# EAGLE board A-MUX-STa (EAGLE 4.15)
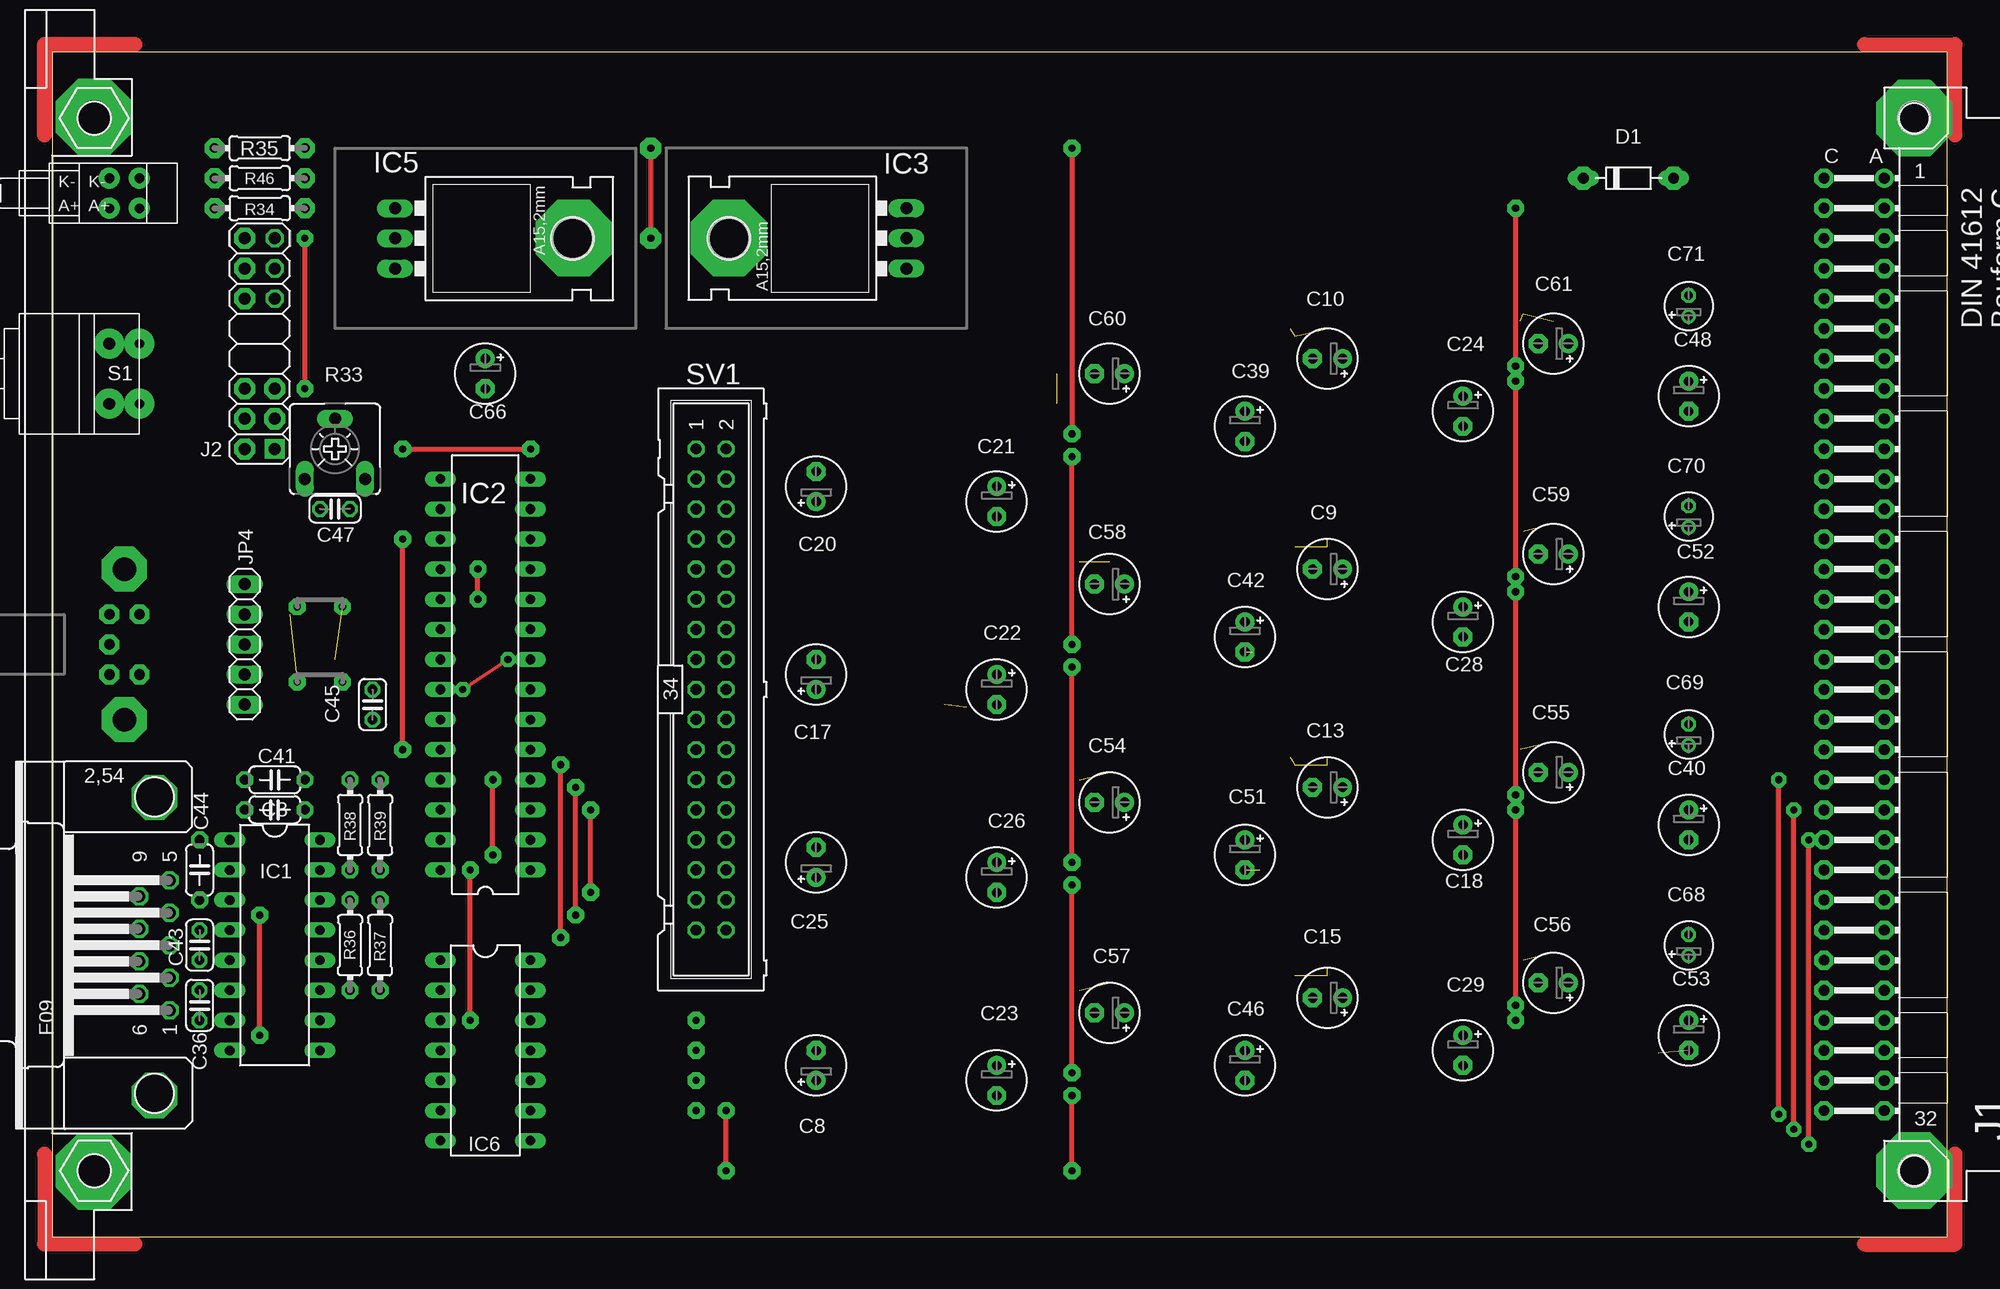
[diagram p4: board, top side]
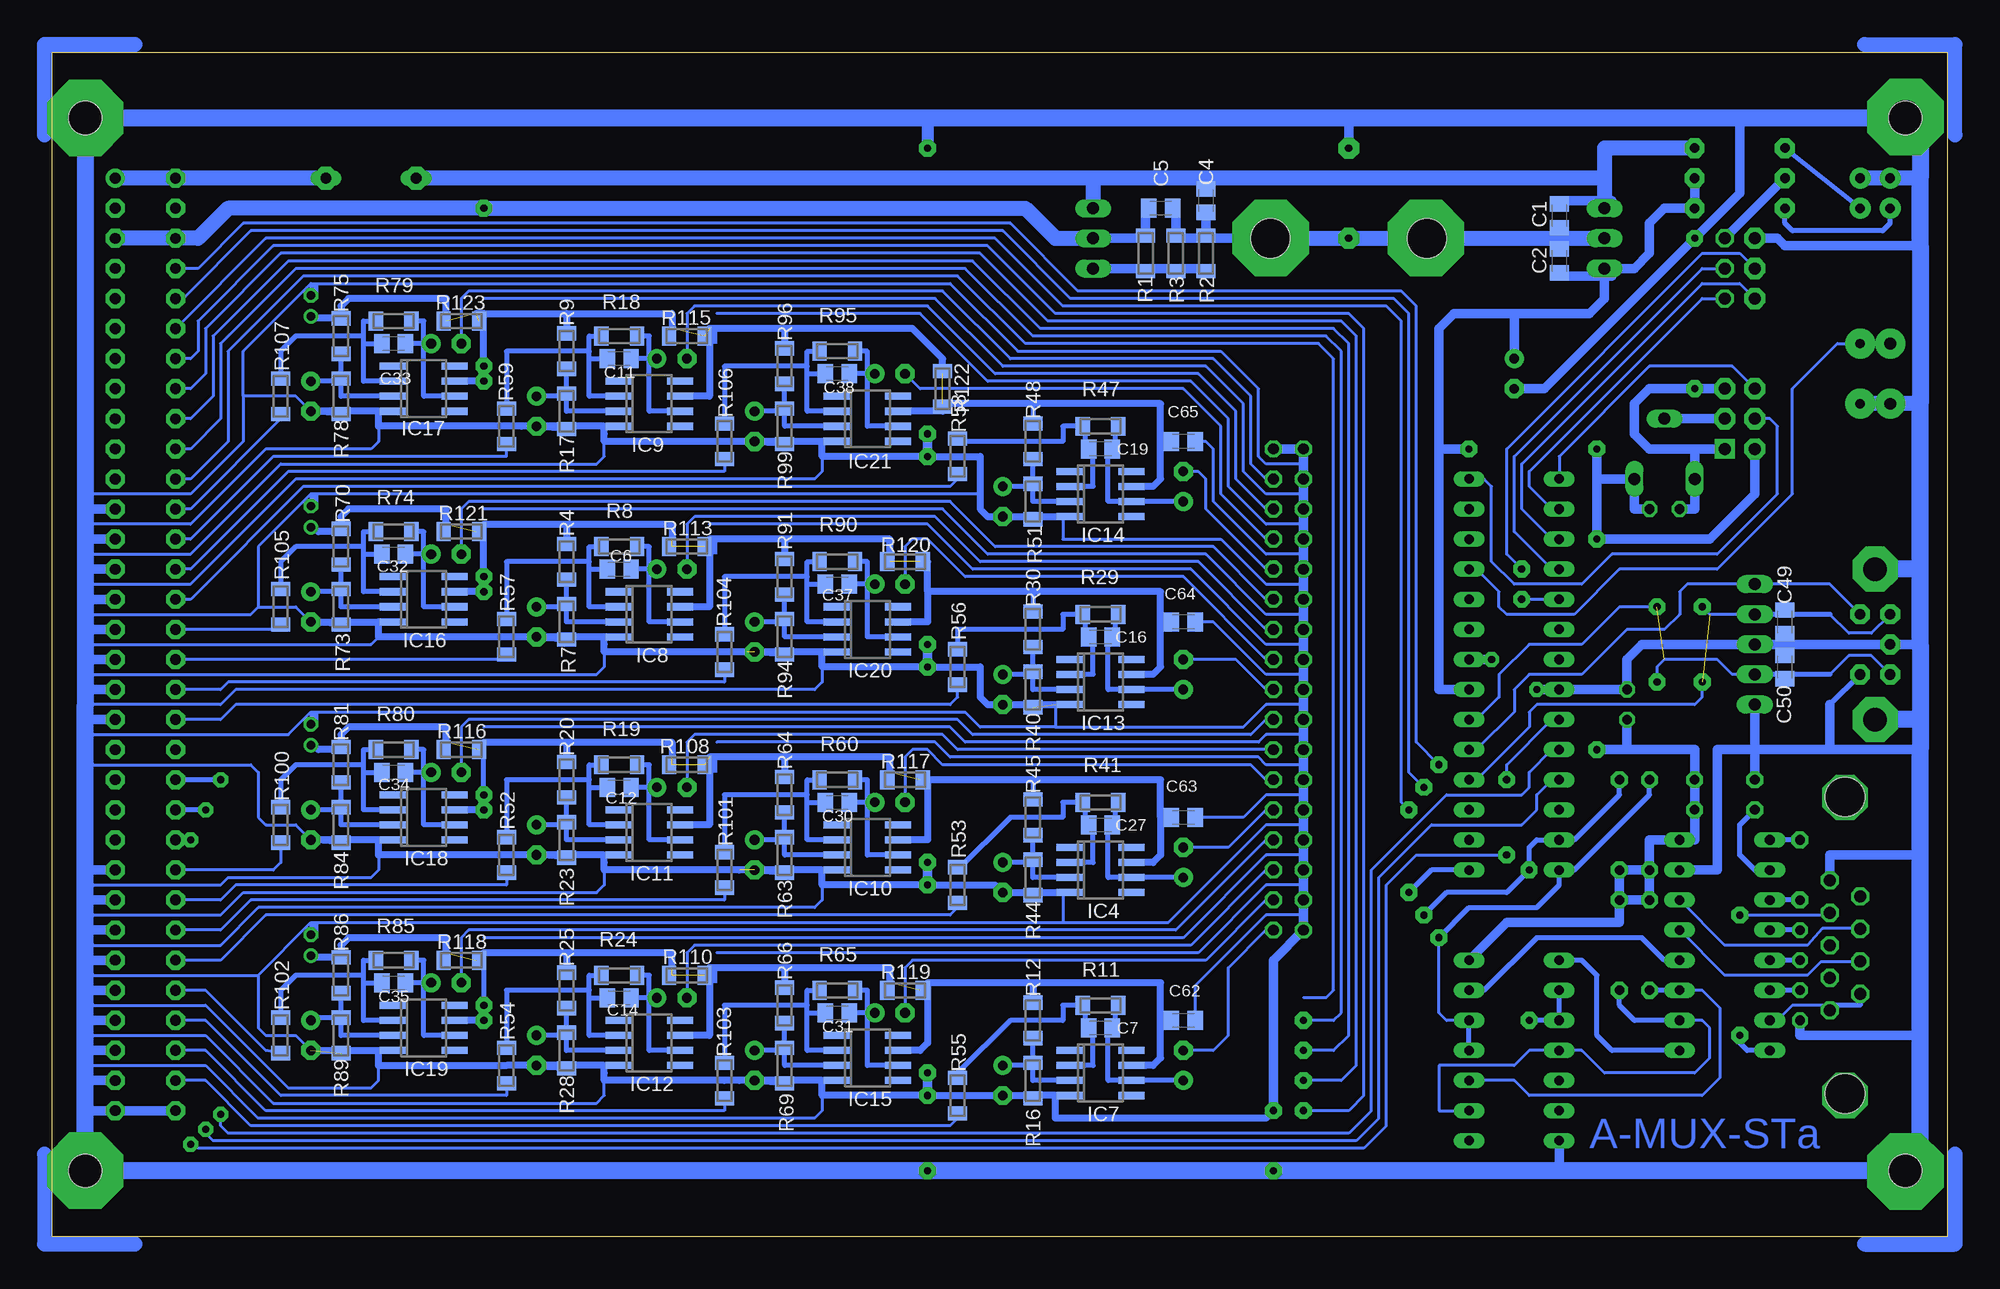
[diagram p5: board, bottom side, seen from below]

Size 160.02 x 100.03 mm. Coordinates in mm from the lower left corner, seen from the top.
Copper layers (1*16): Top 0.035mm / dielectric 1.5mm / Bottom 0.035mm
Design rules "default": minimum track width 10mil, minimum drill 24mil, track to track 8mil, track to pad 8mil, pad to pad 8mil, via to via 8mil, smd to smd 8mil, copper to edge 40mil, drill to drill 8mil, minimum pad ring 10mil, minimum via ring 8mil, stop-mask expansion 4mil, vias tented up to drill 0mil, thermal gap 10mil

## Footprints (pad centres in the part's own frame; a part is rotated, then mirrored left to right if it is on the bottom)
C0805K = smd 1.3 x 1.6: 1 -1,0; 2 1,0
C050-024X044 = drill 0.813 octagon: 1 -2.54,0; 2 2.54,0
E2,5-5 = drill 0.813 pad 1.6 round: + -1.27,0 | drill 0.813 pad 1.6 octagon: - 1.27,0
C025-024X044 = drill 0.813 octagon: 1 -1.27,0; 2 1.27,0
E1,8-4 = drill 0.711 pad 1.168 round: + -0.889,0 | drill 0.711 pad 1.168 octagon: - 0.889,0
D-7.5 = drill 0.813 long: A 3.81,0; C -3.81,0
DIL16 = drill 0.813 long: 1 -8.89,-3.81; 2 -6.35,-3.81; 3 -3.81,-3.81; 4 -1.27,-3.81; 5 1.27,-3.81; 6 3.81,-3.81; 7 6.35,-3.81; 8 8.89,-3.81; 9 8.89,3.81; 10 6.35,3.81; 11 3.81,3.81; 12 1.27,3.81; 13 -1.27,3.81; 14 -3.81,3.81; 15 -6.35,3.81; 16 -8.89,3.81
DIL28-3 = drill 0.813 long: 1 -16.51,-3.81; 2 -13.97,-3.81; 3 -11.43,-3.81; 4 -8.89,-3.81; 5 -6.35,-3.81; 6 -3.81,-3.81; 7 -1.27,-3.81; 8 1.27,-3.81; 9 3.81,-3.81; 10 6.35,-3.81; 11 8.89,-3.81; 12 11.43,-3.81; 13 13.97,-3.81; 14 16.51,-3.81; 15 16.51,3.81; 16 13.97,3.81; 17 11.43,3.81; 18 8.89,3.81; 19 6.35,3.81; 20 3.81,3.81; 21 1.27,3.81; 22 -1.27,3.81; 23 -3.81,3.81; 24 -6.35,3.81; 25 -8.89,3.81; 26 -11.43,3.81; 27 -13.97,3.81; 28 -16.51,3.81
317TL = drill 1.016 long: 1 -2.54,-3.81; 2 0,-3.81; 3 2.54,-3.81 | hole 3.302: 0,11.176
SO08 = smd 0.6 x 2.2: 1 -1.905,-2.6; 2 -0.635,-2.6; 3 0.635,-2.6; 4 1.905,-2.6; 5 1.905,2.6; 6 0.635,2.6; 7 -0.635,2.6; 8 -1.905,2.6
78XXL = drill 1.016 long: GND 0,-3.81; IN -2.54,-3.81; OUT 2.54,-3.81 | hole 3.302: 0,11.176
DIL14 = drill 0.813 long: 1 -7.62,-3.81; 2 -5.08,-3.81; 3 -2.54,-3.81; 4 0,-3.81; 5 2.54,-3.81; 6 5.08,-3.81; 7 7.62,-3.81; 8 7.62,3.81; 9 5.08,3.81; 10 2.54,3.81; 11 0,3.81; 12 -2.54,3.81; 13 -5.08,3.81; 14 -7.62,3.81
VG64P = drill 0.914 pad 1.6 round: A1 154.94,39.37 | drill 0.914 pad 1.6 octagon: A2 154.94,36.83; A3 154.94,34.29; A4 154.94,31.75; A5 154.94,29.21; A6 154.94,26.67; A7 154.94,24.13; A8 154.94,21.59; A9 154.94,19.05; A10 154.94,16.51; A11 154.94,13.97; A12 154.94,11.43; A13 154.94,8.89; A14 154.94,6.35; A15 154.94,3.81; A16 154.94,1.27; A17 154.94,-1.27; A18 154.94,-3.81; A19 154.94,-6.35; A20 154.94,-8.89; A21 154.94,-11.43; A22 154.94,-13.97; A23 154.94,-16.51; A24 154.94,-19.05; A25 154.94,-21.59; A26 154.94,-24.13; A27 154.94,-26.67; A28 154.94,-29.21; A29 154.94,-31.75; A30 154.94,-34.29; A31 154.94,-36.83; A32 154.94,-39.37; C1 149.86,39.37; C2 149.86,36.83; C3 149.86,34.29; C4 149.86,31.75; C5 149.86,29.21; C6 149.86,26.67; C7 149.86,24.13; C8 149.86,21.59; C9 149.86,19.05; C10 149.86,16.51; C11 149.86,13.97; C12 149.86,11.43; C13 149.86,8.89; C14 149.86,6.35; C15 149.86,3.81; C16 149.86,1.27; C17 149.86,-1.27; C18 149.86,-3.81; C19 149.86,-6.35; C20 149.86,-8.89; C21 149.86,-11.43; C22 149.86,-13.97; C23 149.86,-16.51; C24 149.86,-19.05; C25 149.86,-21.59; C26 149.86,-24.13; C27 149.86,-26.67; C28 149.86,-29.21; C29 149.86,-31.75; C30 149.86,-34.29; C31 149.86,-36.83; C32 149.86,-39.37 | hole 2.794: 3.81,44.45; 3.81,-44.45; 157.48,44.45; 157.48,-44.45
2X3-2X3 = drill 1.016 octagon: 1 0,-10.16; 2 -2.54,-10.16; 3 0,-7.62; 4 -2.54,-7.62; 5 0,-5.08; 6 -2.54,-5.08; 11 0,2.54; 12 -2.54,2.54; 13 0,5.08; 14 -2.54,5.08; 15 0,7.62; 16 -2.54,7.62
1X05 = drill 1.016 long: 1 -5.08,0; 2 -2.54,0; 3 0,0; 4 2.54,0; 5 5.08,0
FESLED1 = drill 0.813 pad 1.778 round: A 5.08,-1.27; A1 5.08,-1.27; K 5.08,1.27; K1 5.08,1.27
MINI_MELF-0204W = smd 1.2 x 1.6: 1 -1.5,0; 2 1.5,0
CA6V = drill 1.016 long: A -2.54,-2.54; E 2.54,-2.54; S 0,2.54
0204/7 = drill 0.813 octagon: 1 -3.81,0; 2 3.81,0
MARQ = drill 0.8 pad 2.54 round: 1 0,5.08; 2 0,0 | drill 1 pad 2.54 round: 3 -2.54,5.08; 4 -2.54,0
ML34 = drill 0.914 octagon: 1 -20.32,-1.27; 2 -20.32,1.27; 3 -17.78,-1.27; 4 -17.78,1.27; 5 -15.24,-1.27; 6 -15.24,1.27; 7 -12.7,-1.27; 8 -12.7,1.27; 9 -10.16,-1.27; 10 -10.16,1.27; 11 -7.62,-1.27; 12 -7.62,1.27; 13 -5.08,-1.27; 14 -5.08,1.27; 15 -2.54,-1.27; 16 -2.54,1.27; 17 0,-1.27; 18 0,1.27; 19 2.54,-1.27; 20 2.54,1.27; 21 5.08,-1.27; 22 5.08,1.27; 23 7.62,-1.27; 24 7.62,1.27; 25 10.16,-1.27; 26 10.16,1.27; 27 12.7,-1.27; 28 12.7,1.27; 29 15.24,-1.27; 30 15.24,1.27; 31 17.78,-1.27; 32 17.78,1.27; 33 20.32,-1.27; 34 20.32,1.27
F09H = drill 1.016 octagon: 1 -5.486,-1.27; 2 -2.743,-1.27; 3 0,-1.27; 4 2.743,-1.27; 5 5.486,-1.27; 6 -4.115,1.27; 7 -1.372,1.27; 8 1.372,1.27; 9 4.115,1.27 | hole 3.302: -12.522,0; 12.522,0

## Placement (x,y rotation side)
C1  100n  [C0805K]  32.77,86.21 270 bottom
C2  100n  [C0805K]  32.77,82.4 90 bottom
C3  100n  [C050-024X044]  18.8,36.04 180 top
C4  100n  [C0805K]  62.61,87.48 270 bottom
C5  100n  [C0805K]  66.42,86.84 0 bottom
C6  68p  [C0805K]  112.14,56.36 0 bottom
C7  68p  [C0805K]  71.5,17.63 0 bottom
C8  4,7u  [E2,5-5]  64.52,14.45 90 top
C9  4,7u  [E2,5-5]  107.7,56.36 180 top
C10  4,7u  [E2,5-5]  107.7,74.14 180 top
C11  68p  [C0805K]  112.14,74.14 0 bottom
C12  68p  [C0805K]  112.14,37.95 0 bottom
C13  4,7u  [E2,5-5]  107.7,37.95 180 top
C14  68p  [C0805K]  112.14,20.17 0 bottom
C15  4,7u  [E2,5-5]  107.7,20.17 180 top
C16  68p  [C0805K]  71.5,50.65 0 bottom
C17  4,7u  [E2,5-5]  64.52,47.47 90 top
C18  10u  [E2,5-5]  119.13,33.5 270 top
C19  68p  [C0805K]  71.5,66.52 0 bottom
C20  4,7u  [E2,5-5]  64.52,63.35 90 top
C21  10u  [E2,5-5]  79.76,62.08 270 top
C22  10u  [E2,5-5]  79.76,46.2 270 top
C23  10u  [E2,5-5]  79.76,13.18 270 top
C24  10u  [E2,5-5]  119.13,69.7 270 top
C25  4,7u  [E2,5-5]  64.52,31.6 90 top
C26  10u  [E2,5-5]  79.76,30.33 270 top
C27  68p  [C0805K]  71.5,34.77 0 bottom
C28  10u  [E2,5-5]  119.13,51.92 270 top
C29  10u  [E2,5-5]  119.13,15.72 270 top
C30  68p  [C0805K]  93.73,36.68 0 bottom
C31  68p  [C0805K]  93.73,18.9 0 bottom
C32  68p  [C0805K]  131.19,57.63 0 bottom
C33  68p  [C0805K]  131.19,75.41 0 bottom
C34  68p  [C0805K]  131.19,39.22 0 bottom
C35  68p  [C0805K]  131.19,21.44 0 bottom
C36  100n  [C025-024X044]  12.45,19.53 270 top
C37  68p  [C0805K]  93.73,55.09 0 bottom
C38  68p  [C0805K]  93.73,72.87 0 bottom
C39  10u  [E2,5-5]  100.71,68.43 270 top
C40  10u  [E2,5-5]  138.18,34.77 270 top
C41  100n  [C050-024X044]  18.8,38.58 0 top
C42  10u  [E2,5-5]  100.71,50.65 270 top
C43  100n  [C025-024X044]  12.45,24.61 90 top
C44  100n  [C050-024X044]  12.45,30.96 90 top
C45  100n  [C025-024X044]  27.05,44.93 270 top
C46  10u  [E2,5-5]  100.71,14.45 270 top
C47  100n  [C025-024X044]  23.88,61.44 180 top
C48  10u  [E2,5-5]  138.18,70.97 270 top
C49  100n  [C0805K]  13.72,51.92 90 bottom
C50  100n  [C0805K]  13.72,48.11 270 bottom
C51  10u  [E2,5-5]  100.71,32.23 270 top
C52  10u  [E2,5-5]  138.18,53.19 270 top
C53  10u  [E2,5-5]  138.18,16.99 270 top
C54  4,7u  [E2,5-5]  89.28,36.68 180 top
C55  4,7u  [E2,5-5]  126.75,39.22 180 top
C56  4,7u  [E2,5-5]  126.75,21.44 180 top
C57  4,7u  [E2,5-5]  89.28,18.9 180 top
C58  4,7u  [E2,5-5]  89.28,55.09 180 top
C59  4,7u  [E2,5-5]  126.75,57.63 180 top
C60  4,7u  [E2,5-5]  89.28,72.87 180 top
C61  4,7u  [E2,5-5]  126.75,75.41 180 top
C62  100n  [C0805K]  64.52,18.26 180 bottom
C63  100n  [C0805K]  64.52,35.41 180 bottom
C64  100n  [C0805K]  64.52,51.92 180 bottom
C65  100n  [C0805K]  64.52,67.16 180 bottom
C66  10u  [E2,5-5]  36.58,72.87 270 top
C68  4,7U  [E1,8-4]  138.18,24.61 90 top
C69  4,7u  [E1,8-4]  138.18,42.39 90 top
C70  4,7u  [E1,8-4]  138.18,60.81 90 top
C71  4,7u  [E1,8-4]  138.18,78.59 90 top
D1  1N4007  [D-7.5]  133.1,89.38 0 top
IC1  MAX232A  [DIL16]  18.8,24.61 270 top
IC2  MEGA8-P  [DIL28-3]  36.58,47.47 90 top
IC3  LM317  [317TL]  68.33,84.3 90 top
IC4  TL061CD  [SO08]  71.5,30.96 270 bottom
IC5  7805  [78XXL]  32.77,84.3 270 top
IC6  74AC06N  [DIL14]  36.58,15.72 270 top
IC7  TL061CD  [SO08]  71.5,13.82 270 bottom
IC8  TL061CD  [SO08]  109.6,52.55 270 bottom
IC9  TL061CD  [SO08]  109.6,70.33 270 bottom
IC10  TL061CD  [SO08]  91.19,32.87 270 bottom
IC11  TL061CD  [SO08]  109.6,34.14 270 bottom
IC12  TL061CD  [SO08]  109.6,16.36 270 bottom
IC13  TL061CD  [SO08]  71.5,46.84 270 bottom
IC14  TL061CD  [SO08]  71.5,62.71 270 bottom
IC15  TL061CD  [SO08]  91.19,15.09 270 bottom
IC16  TL061CD  [SO08]  128.65,53.82 270 bottom
IC17  TL061CD  [SO08]  128.65,71.6 270 bottom
IC18  TL061CD  [SO08]  128.65,35.41 270 bottom
IC19  TL061CD  [SO08]  128.65,17.63 270 bottom
IC20  TL061CD  [SO08]  91.19,51.28 270 bottom
IC21  TL061CD  [SO08]  91.19,69.06 270 bottom
J1  VG Leiste  [VG64P]  -0.25,50.01 0 top
J2  St.-LCD  [2X3-2X3]  18.8,76.68 0 top
JP4  [1X05]  16.26,50.01 270 top
LED1  FESLED1  [FESLED1]  -0.25,88.11 0 top
LED2  FESLED1  [FESLED1]  2.29,88.11 0 top
R1  240  [MINI_MELF-0204W]  67.69,83.03 270 bottom
R2  [MINI_MELF-0204W]  62.61,83.03 90 bottom
R3  [MINI_MELF-0204W]  65.15,83.03 90 bottom
R4  12K  [MINI_MELF-0204W]  116.59,57 90 bottom
R7  12K  [MINI_MELF-0204W]  116.59,51.92 90 bottom
R8  68K  [MINI_MELF-0204W]  112.14,58.27 0 bottom
R9  12K  [MINI_MELF-0204W]  116.59,74.78 90 bottom
R11  68K  [MINI_MELF-0204W]  71.5,19.53 0 bottom
R12  12K  [MINI_MELF-0204W]  77.22,18.26 90 bottom
R16  12K  [MINI_MELF-0204W]  77.22,13.18 90 bottom
R17  12K  [MINI_MELF-0204W]  116.59,69.7 90 bottom
R18  68K  [MINI_MELF-0204W]  112.14,76.05 0 bottom
R19  68K  [MINI_MELF-0204W]  112.14,39.85 0 bottom
R20  12K  [MINI_MELF-0204W]  116.59,38.58 90 bottom
R23  12K  [MINI_MELF-0204W]  116.59,33.5 90 bottom
R24  68K  [MINI_MELF-0204W]  112.14,22.07 0 bottom
R25  12K  [MINI_MELF-0204W]  116.59,20.8 90 bottom
R28  12K  [MINI_MELF-0204W]  116.59,15.72 90 bottom
R29  68K  [MINI_MELF-0204W]  71.5,52.55 0 bottom
R30  12K  [MINI_MELF-0204W]  77.22,51.28 90 bottom
R33  10K  [CA6V]  23.88,66.52 0 top
R34  470  [0204/7]  17.53,86.84 180 top
R35  2,2K  [0204/7]  17.53,91.92 0 top
R36  10K  [0204/7]  25.15,24.61 90 top
R37  10K  [0204/7]  27.69,24.61 90 top
R38  10K  [0204/7]  25.15,34.77 270 top
R39  10K  [0204/7]  27.69,34.77 270 top
R40  12K  [MINI_MELF-0204W]  77.22,46.2 90 bottom
R41  68K  [MINI_MELF-0204W]  71.5,36.68 0 bottom
R44  12K  [MINI_MELF-0204W]  77.22,30.33 90 bottom
R45  12K  [MINI_MELF-0204W]  77.22,35.41 90 bottom
R46  22  [0204/7]  17.53,89.38 180 top
R47  68K  [MINI_MELF-0204W]  71.5,68.43 0 bottom
R48  12K  [MINI_MELF-0204W]  77.22,67.16 90 bottom
R51  12K  [MINI_MELF-0204W]  77.22,62.08 90 bottom
R52  000  [MINI_MELF-0204W]  121.67,32.23 90 bottom
R53  000  [MINI_MELF-0204W]  83.57,29.69 90 bottom
R54  000  [MINI_MELF-0204W]  121.67,14.45 90 bottom
R55  000  [MINI_MELF-0204W]  83.57,11.91 90 bottom
R56  000  [MINI_MELF-0204W]  83.57,48.11 90 bottom
R57  000  [MINI_MELF-0204W]  121.67,50.65 90 bottom
R58  000  [MINI_MELF-0204W]  83.57,65.89 90 bottom
R59  000  [MINI_MELF-0204W]  121.67,68.43 90 bottom
R60  68K  [MINI_MELF-0204W]  93.73,38.58 0 bottom
R63  12K  [MINI_MELF-0204W]  98.17,32.23 90 bottom
R64  12K  [MINI_MELF-0204W]  98.17,37.31 90 bottom
R65  68K  [MINI_MELF-0204W]  93.73,20.8 0 bottom
R66  12K  [MINI_MELF-0204W]  98.17,19.53 90 bottom
R69  12K  [MINI_MELF-0204W]  98.17,14.45 90 bottom
R70  12K  [MINI_MELF-0204W]  135.64,58.27 90 bottom
R73  12K  [MINI_MELF-0204W]  135.64,53.19 90 bottom
R74  68K  [MINI_MELF-0204W]  131.19,59.54 0 bottom
R75  12K  [MINI_MELF-0204W]  135.64,76.05 90 bottom
R78  12K  [MINI_MELF-0204W]  135.64,70.97 90 bottom
R79  68K  [MINI_MELF-0204W]  131.19,77.32 0 bottom
R80  68K  [MINI_MELF-0204W]  131.19,41.12 0 bottom
R81  12K  [MINI_MELF-0204W]  135.64,39.85 90 bottom
R84  12K  [MINI_MELF-0204W]  135.64,34.77 90 bottom
R85  68K  [MINI_MELF-0204W]  131.19,23.34 0 bottom
R86  12K  [MINI_MELF-0204W]  135.64,22.07 90 bottom
R89  12K  [MINI_MELF-0204W]  135.64,16.99 90 bottom
R90  68K  [MINI_MELF-0204W]  93.73,57 0 bottom
R91  12K  [MINI_MELF-0204W]  98.17,55.73 90 bottom
R94  12K  [MINI_MELF-0204W]  98.17,50.65 90 bottom
R95  68K  [MINI_MELF-0204W]  93.73,74.78 0 bottom
R96  12K  [MINI_MELF-0204W]  98.17,73.51 90 bottom
R99  12K  [MINI_MELF-0204W]  98.17,68.43 90 bottom
R100  000  [MINI_MELF-0204W]  140.72,34.77 90 bottom
R101  000  [MINI_MELF-0204W]  103.25,30.96 90 bottom
R102  000  [MINI_MELF-0204W]  140.72,16.99 90 bottom
R103  000  [MINI_MELF-0204W]  103.25,13.18 90 bottom
R104  000  [MINI_MELF-0204W]  103.25,49.38 90 bottom
R105  000  [MINI_MELF-0204W]  140.72,53.19 90 bottom
R106  000  [MINI_MELF-0204W]  103.25,67.16 90 bottom
R107  000  [MINI_MELF-0204W]  140.72,70.97 90 bottom
R108  000  [MINI_MELF-0204W]  106.43,39.85 0 bottom
R110  000  [MINI_MELF-0204W]  106.43,22.07 0 bottom
R113  000  [MINI_MELF-0204W]  106.43,58.27 0 bottom
R115  000  [MINI_MELF-0204W]  106.43,76.05 0 bottom
R116  000  [MINI_MELF-0204W]  125.48,41.12 0 bottom
R117  000  [MINI_MELF-0204W]  88.01,38.58 0 bottom
R118  000  [MINI_MELF-0204W]  125.48,23.34 0 bottom
R119  000  [MINI_MELF-0204W]  88.01,20.8 0 bottom
R120  000  [MINI_MELF-0204W]  88.01,57 0 bottom
R121  000  [MINI_MELF-0204W]  125.48,59.54 0 bottom
R122  000  [MINI_MELF-0204W]  84.84,71.6 270 bottom
R123  000  [MINI_MELF-0204W]  125.48,77.32 0 bottom
S1  Taster  [MARQ]  7.37,70.33 0 top
SV1  W-Stecker  [ML34]  55.63,46.2 270 top
U$2  [DINA4_L]  not placed on the board
X1  DSUB  [F09H]  8.64,24.61 90 top

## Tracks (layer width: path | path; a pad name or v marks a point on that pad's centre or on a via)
+8V  (via drill 0.6 pad 1.42)  (18 unrouted)
  Top 0.406: v123.57,19.53 v123.57,36.04 | v123.57,37.31 v123.57,54.46 | v123.57,55.73 v123.57,72.24 | v123.57,73.51 v123.57,86.84
  Bottom 0.254: R113.1 107.7,58.27 | R120.1 89.28,57 | R108.1 107.7,39.85 | R110.1 107.7,22.07 | 104.52,22.71 104.52,22.07 R110.2 | R118.2 124.21,23.34 | R117.2 86.74,38.58 | 66.42,67.16 C65.2 | R120.2 86.74,57
  Bottom 0.406: 107.7,76.68 R115.1 | R123.1 126.75,77.32 | 123.57,60.17 R121.2 124.21,59.54 | R121.1 126.75,60.17 | R119.1 89.28,21.44 | 86.11,57 R120.2 | R117.1 89.28,39.22 | R116.2 123.57,41.76 v123.57,37.31 | R116.1 126.75,41.76 | R118.2 123.57,23.98 v123.57,19.53 | R118.1 126.75,23.98 | R117.2 86.11,38.58 86.74,38.58 | 104.52,58.9 104.52,58.27 R113.2 | 77.22,68.43 R48.2 77.22,70.33 | 77.22,52.55 R30.2 77.22,54.46 | 77.22,36.68 R45.2 77.22,38.58 | 77.22,19.53 R12.2 | R119.2 86.74,20.8
  Bottom 0.61: 116.59,77.95 107.7,77.95 107.7,76.68 | 123.57,77.95 116.59,77.95 | 123.57,77.95 124.21,77.95 | 126.75,77.32 126.75,79.22 135,79.22 135.64,78.59 R75.2 137.77,77.55 138.18,77.95 C71.+ | 135.64,60.81 135,61.44 126.75,61.44 126.75,60.17 | 135.64,60.81 R70.2 | 116.59,60.17 107.7,60.17 107.7,58.9 | 116.59,60.17 123.57,60.17 v123.57,55.73 v123.57,54.46 IC16.7 | 98.17,22.71 R66.2 | 98.17,22.71 89.28,22.71 89.28,21.44 | 98.17,22.71 104.52,22.71 104.52,16.99 IC12.7 | 86.11,54.46 86.11,57 | 86.11,54.46 77.22,54.46 66.42,54.46 66.42,51.92 | 66.42,51.92 66.42,48.11 67.06,47.47 IC13.7 69.6,47.47 | 86.11,54.46 86.11,51.92 IC20.7 | 98.17,58.9 R91.2 | 98.17,58.9 89.28,58.9 89.28,57 | 98.17,58.9 104.52,58.9 104.52,53.19 IC8.7 | 98.17,76.68 R96.2 | 98.17,76.68 87.38,76.68 84.84,74.14 R122.1 84.84,72.87 | 98.17,76.68 104.52,76.68 104.52,70.97 IC9.7 107.06,70.97 | 98.17,40.49 R64.2 | 98.17,40.49 89.28,40.49 89.28,39.22 | 98.17,40.49 104.52,40.49 104.52,34.77 IC11.7 | 116.59,41.76 107.7,41.76 107.7,40.49 | 135.64,42.39 135,43.03 126.75,43.03 126.75,41.76 | 135.64,42.39 R81.2 | 123.57,41.76 116.59,41.76 | 107.7,22.71 107.7,23.98 116.59,23.98 | 126.75,23.98 126.75,25.25 135,25.25 135.64,24.61 R86.2 137.77,23.57 138.18,23.98 C68.+ | 116.59,23.98 123.57,23.98 | IC21.7 84.84,69.7 R122.2 84.84,70.33 77.22,70.33 66.42,70.33 66.42,67.16 66.42,63.98 67.06,63.35 IC14.7 | IC17.7 v123.57,72.24 v123.57,73.51 123.57,77.95 | v123.57,37.31 v123.57,36.04 IC18.7 | 116.59,41.76 R20.2 | IC10.7 86.11,33.5 86.11,38.58 77.22,38.58 66.42,38.58 66.42,35.41 | IC4.7 67.06,31.6 66.42,32.23 66.42,35.41 | v123.57,19.53 v123.57,18.26 IC19.7
  Bottom 0.61: IC15.7 86.74,15.72 86.11,16.36 86.11,21.44 | R119.2 86.11,20.8 86.11,21.44 | 67.69,14.45 IC7.7 67.06,14.45 66.42,15.09 66.42,18.26 | 66.42,18.26 66.42,21.44 77.22,21.44 | 77.22,21.44 86.11,21.44 | 116.59,23.98 R25.2 | 77.22,21.44 77.22,19.53 | 116.59,77.95 R9.2 | 116.59,60.17 R4.2 | 66.42,51.92 C64.2 | C63.2 66.42,35.41 | 66.42,18.26 C62.2 | 135.64,42.39 135.64,41.12 137.54,41.12 138.18,41.76 C69.+ | 135.64,60.81 135.64,59.54 137.54,59.54 138.18,60.17 C70.+
  Bottom 0.813: IC3.2 67.69,84.3 | 67.69,84.3 67.69,86.84 C5.1 | 67.69,84.3 R1.1 | v123.57,19.53 v123.57,18.26 | v123.57,36.04 v123.57,37.31 | v123.57,54.46 v123.57,55.73 | v123.57,72.24 v123.57,73.51
  Bottom 1.27: J1.A3 J1.C3 147.7,84.3 145.16,86.84 v123.57,86.84 77.85,86.84 75.31,84.3 IC3.2
A  (via drill 0.6 pad 1.42)
  Bottom 0.254: v54.36,10.64 50.55,10.64 49.28,11.91 49.28,76.68 50.55,77.95 75.31,77.95 81.03,83.67 141.35,83.67 147.7,77.32 147.7,74.78 148.34,74.14 J1.C7
A1
  Bottom 0.254: SV1.22 83.57,41.12 84.84,42.39 105.79,42.39 106.43,41.76 C13.-
A2
  Bottom 0.254: SV1.26 57.53,36.04 60.71,32.87 C25.-
A3
  Bottom 0.254: C15.- 106.43,23.98 105.79,24.61 63.88,24.61 57.53,30.96 SV1.30
A4
  Bottom 0.254: C8.- 61.98,15.72 60.71,16.99 60.71,22.71 57.53,25.88 SV1.34
A5
  Bottom 0.254: SV1.18 57.53,46.2 60.07,48.74 C17.-
A6
  Bottom 0.254: SV1.14 57.53,51.28 63.25,57 81.66,57 85.47,60.81 105.79,60.81 106.43,60.17 C9.-
A7
  Bottom 0.254: SV1.10 57.53,56.36 62.61,61.44 62.61,63.98 63.25,64.62 C20.-
A8
  Bottom 0.254: SV1.6 57.53,61.44 60.07,63.98 60.07,69.7 63.25,72.87 80.39,72.87 86.11,78.59 105.79,78.59 106.43,77.95 C10.-
A9
  Bottom 0.254: C55.- 125.48,43.03 124.84,43.66 83.57,43.66 82.3,42.39 58.8,42.39 57.53,43.66 SV1.20
A10
  Bottom 0.254: C54.- 88.01,40.49 87.38,41.12 86.11,41.12 84.84,39.85 58.8,39.85 57.53,38.58 SV1.24
A11
  Bottom 0.254: C56.- 125.48,25.25 124.84,25.88 65.15,25.88 57.53,33.5 SV1.28
A12
  Bottom 0.254: C57.- 88.01,22.71 87.38,23.34 62.61,23.34 57.53,28.42 SV1.32
A13
  Bottom 0.254: C58.- 88.01,58.27 87.38,58.9 86.11,58.9 82.93,55.73 64.52,55.73 57.53,48.74 SV1.16
A14
  Bottom 0.254: C59.- 125.48,61.44 124.84,62.08 84.2,62.08 80.39,58.27 61.98,58.27 57.53,53.82 SV1.12
A15
  Bottom 0.254: SV1.8 57.53,58.9 61.34,62.71 61.34,68.43 64.52,71.6 86.74,71.6 C60.-
A16
  Bottom 0.254: C61.- 125.48,79.22 124.84,79.86 84.84,79.86 79.12,74.14 61.98,74.14 58.8,70.97 58.8,65.25 57.53,63.98 SV1.4
B  (via drill 0.6 pad 1.42)
  Bottom 0.254: v54.36,13.18 51.18,13.18 49.91,14.45 49.91,76.05 51.18,77.32 75.95,77.32 81.66,83.03 140.72,83.03 147.07,76.68 147.07,72.87 148.34,71.6 J1.C8
C  (via drill 0.6 pad 1.42)
  Bottom 0.254: J1.C9 148.34,69.06 146.43,70.97 146.43,76.05 140.08,82.4 82.3,82.4 76.58,76.68 51.82,76.68 50.55,75.41 50.55,16.99 51.82,15.72 v54.36,15.72
CL  (via drill 0.6 pad 1.27, 0.6 pad 1.42)
  Top 0.406: v37.21,32.23 v37.21,38.58 | v148.34,7.79 v148.34,33.5
  Bottom 0.254: v37.21,38.58 37.21,39.85 33.4,43.66 IC2.23 | v148.34,7.79 147.7,7.47 49.28,7.47 47.37,9.37 47.37,29.69 44.83,32.23 v37.21,32.23
  Bottom 0.406: v148.34,33.5 J1.C23
D  (via drill 0.6 pad 1.42)
  Bottom 0.254: J1.C10 148.34,66.52 145.8,69.06 145.8,75.41 139.45,81.76 82.93,81.76 77.22,76.05 52.45,76.05 51.18,74.78 51.18,18.9 51.82,18.26 v54.36,18.26
DA  (via drill 0.6 pad 1.27)
  Top 0.406: v145.8,10.32 v145.8,38.58
  Bottom 0.254: IC2.24 33.4,41.12 35.31,39.22 35.31,37.95 35.94,37.31 42.29,37.31 48.64,30.96 48.64,10.64 50.55,8.74 145.16,8.74 145.8,9.37 v145.8,10.32
  Bottom 0.406: v145.8,38.58 J1.C21
E
  Bottom 0.254: J1.C11 148.34,63.98 145.16,67.16 145.16,74.78 138.81,81.13 83.57,81.13 77.85,75.41 53.09,75.41 51.82,74.14 51.82,20.8 52.45,20.17 54.36,20.17
EN  (via drill 0.6 pad 1.27)
  Top 0.406: v147.07,9.05 v147.07,36.04
  Bottom 0.254: IC2.25 33.4,38.58 34.67,37.31 34.67,36.04 35.94,34.77 43.56,34.77 48.01,30.33 48.01,10.01 49.91,8.1 146.43,8.1 147.07,8.74 v147.07,9.05
  Bottom 0.406: v147.07,36.04 J1.C22
GND  (via drill 0.6 pad 1.27, 0.6 pad 1.42, 0.6 pad 1.78, 0.9 pad 1.68, 2 pad 3.81, 2.8 pad 6.45)  (4 unrouted)
  Top 0.254: v34.67,46.2 v38.48,48.74
  Top 0.406: v56.9,5.56 v56.9,10.64 | v86.11,13.82 v86.11,29.69 | v86.11,31.6 v86.11,48.11 | v86.11,50.01 v86.11,65.89 | v86.11,91.92 v86.11,67.79 | v86.11,5.56 v86.11,11.91 | v21.34,84.3 v21.34,71.6 | v50.55,91.92 v50.55,84.3 v50.55,91.92
  Bottom 0.254: IC14.4 74.68,60.81 74.68,58.9 61.34,58.9 57.53,55.09 54.36,55.09 | 74.68,29.06 74.68,26.52 | 74.68,26.52 65.79,26.52 57.53,34.77 54.36,34.77 | 75.31,44.93 75.31,43.03 | 54.36,44.93 57.53,44.93 59.44,43.03 75.31,43.03 | J1.A13 154.37,58.9 | 157.23,19.53 157.23,18.26 | 157.23,19.53 157.23,20.8 157.23,22.07 | 157.23,50.01 157.23,48.74 157.23,46.2 157.23,43.66 | 157.23,50.01 157.23,51.28 157.23,53.82 157.23,55.09 | 157.23,60.17 157.23,58.9 | 157.23,60.17 157.23,61.44 157.23,62.71 148.34,62.71 143.89,67.16 143.89,70.97 | 54.36,29.69 57.53,29.69 63.25,23.98 103.89,23.98 | 54.36,32.23 57.53,32.23 64.52,25.25 123.57,25.25 | 138.18,26.52 74.68,26.52 | 54.36,62.71 57.53,62.71 59.44,64.62 59.44,70.33 62.61,73.51 79.76,73.51 85.47,79.22 123.57,79.22 | 54.36,60.17 57.53,60.17 60.71,63.35 60.71,69.06 63.88,72.24 81.03,72.24 86.74,77.95 103.89,77.95 | 54.36,65.25 57.53,65.25 58.17,65.89 58.17,71.6 61.34,74.78 78.49,74.78 84.2,80.49 138.18,80.49 | 138.18,80.49 143.89,74.78 143.89,70.97 | 157.23,50.01 133.1,50.01 132.46,50.65 | 54.36,39.85 57.53,39.85 58.17,40.49 84.2,40.49 85.47,41.76 103.89,41.76 | 54.36,42.39 57.53,42.39 58.17,41.76 82.93,41.76 84.2,43.03 123.57,43.03 | 157.23,19.53 147.07,19.53 140.08,12.55 133.1,12.55 132.46,13.18 132.46,14.45 | 157.23,14.45 147.07,14.45 142.62,10.01 95.63,10.01 95,10.64 95,11.91 | 157.23,22.07 142.62,22.07 | 54.36,52.55 57.53,52.55 62.61,57.63 81.03,57.63 84.84,61.44 123.57,61.44 | 54.36,50.01 57.53,50.01 63.88,56.36 82.3,56.36 86.11,60.17 104.52,60.17 | 157.23,22.07 157.23,23.34 157.23,25.88 157.23,28.42 157.23,30.96 | 157.23,55.09 157.23,56.36
  Bottom 0.254: 157.23,60.17 148.34,60.17 141.99,66.52 133.1,66.52 132.46,67.16 132.46,69.7 | 56.9,84.3 v50.55,84.3 44.2,84.3 | 157.23,57.63 148.34,57.63 140.72,65.25 114.05,65.25 113.41,65.89 113.41,67.79 | 157.23,55.09 148.34,55.09 139.45,63.98 95.63,63.98 95,64.62 95,65.89 | 157.23,52.55 143.26,52.55 142.62,53.19 | 142.62,53.19 142.62,58.27 138.18,62.71 | 157.23,47.47 114.05,47.47 113.41,48.11 113.41,50.01 | 157.23,44.93 145.8,44.93 144.53,46.2 95.63,46.2 95,46.84 95,48.11 | 157.23,42.39 140.08,42.39 138.18,44.3 | 138.18,44.3 82.93,44.3 81.66,43.03 75.31,43.03 | 157.23,16.99 147.07,16.99 141.35,11.28 114.05,11.28 113.41,11.91 113.41,13.82 | 157.23,29.69 145.8,29.69 145.16,30.33 133.1,30.33 132.46,30.96 132.46,32.87 | 157.23,27.15 145.8,27.15 143.89,29.06 114.05,29.06 113.41,29.69 113.41,31.6 | 157.23,24.61 145.8,24.61 142.62,27.79 95.63,27.79 95,28.42 95,29.69 | 81.66,62.71 138.18,62.71 | 157.23,39.85 143.26,39.85 142.62,39.22 142.62,35.41 141.99,34.77 139.45,34.77 C40.- | 142.62,22.07 138.18,26.52 | 142.62,53.19 139.45,53.19 C52.- | C48.- 139.45,70.97 143.89,70.97 | C53.- 139.45,16.99 141.99,16.99 142.62,17.63 142.62,22.07 | C63.1 59.44,35.41 57.53,37.31 54.36,37.31 | C62.1 63.52,21.17 57.53,27.15 54.36,27.15 | C64.1 61.98,51.92 57.53,47.47 54.36,47.47 | 63.52,66.79 C65.1 62.61,67.16 61.98,66.52 61.98,62.08 57.53,57.63 54.36,57.63 | 138.18,80.49 C71.- | 138.18,62.71 C70.- | 138.18,44.3 C69.- | 138.18,26.52 C68.-
  Bottom 0.406: 133.73,51.92 132.46,51.92 IC16.4 | 120.4,68.43 R17.1 | C48.- R78.1 | 95,67.16 IC21.4 | 101.98,67.16 R99.1 | 101.35,49.38 R94.1 | 95,49.38 IC20.4 | 113.41,50.65 IC8.4 | 121.67,50.65 R7.1 | C52.- R73.1 | 132.46,33.5 IC18.4 | C18.- R23.1 | 95,30.96 IC10.4 | 101.98,30.96 R63.1 | 113.41,32.23 IC11.4 | 95,13.18 IC15.4 | 101.98,13.18 R69.1 | SV1.27 54.36,34.77 SV1.25 | SV1.19 54.36,44.93 SV1.17 | 2.29,61.44 2.29,83.67 2.29,94.46 | v56.9,5.56 2.29,5.56 2.29,50.01 25.78,50.01 | 121.67,14.45 R28.1 | C46.- 103.25,13.18 | C40.- R84.1 | C39.- 103.25,67.16 | 9.91,44.93 v7.37,47.47 | 157.23,10.64 157.23,10.01 | R51.1 77.22,60.81 81.03,60.81 | 77.22,11.91 R16.1 | 77.22,29.06 R44.1
  Bottom 0.61: 113.41,68.43 IC9.4 | 113.41,68.43 C24.- 120.4,68.43 132.46,68.43 132.46,69.7 | 132.46,69.7 IC17.4 | 132.46,69.7 C48.- | 74.68,60.81 77.22,60.81 C21.- 81.03,60.81 81.66,61.44 81.66,62.71 81.66,65.89 v86.11,65.89 95,65.89 95,67.16 C39.- 101.98,67.16 103.25,67.16 113.41,67.16 113.41,67.79 113.41,68.43 | 74.04,44.93 IC13.4 75.31,44.93 C22.- 81.03,44.93 81.66,45.57 81.66,48.11 v86.11,48.11 95,48.11 95,49.38 101.35,49.38 113.41,49.38 113.41,50.01 113.41,50.65 C28.- 121.67,50.65 132.46,50.65 132.46,51.92 C52.- | C40.- 132.46,33.5 132.46,32.87 132.46,32.23 C18.- 113.41,32.23 113.41,31.6 113.41,30.96 101.98,30.96 95,30.96 95,29.69 v86.11,29.69 | IC4.4 74.68,29.06 77.22,29.06 C26.- 80.39,29.69 v86.11,29.69 | 75.31,11.91 IC7.4 | 75.31,11.91 77.22,11.91 C23.- v86.11,11.91 | v86.11,11.91 v86.11,13.82 | v86.11,11.91 v86.11,13.82 | v86.11,11.91 95,11.91 95,13.18 C46.- 101.98,13.18 103.25,13.18 113.41,13.18 113.41,13.82 113.41,14.45 | 113.41,14.45 IC12.4 | 113.41,14.45 C29.- 121.67,14.45 132.46,14.45 132.46,15.72 | 132.46,15.72 IC19.4 | C53.- 132.46,15.72 | 75.31,11.91 75.31,10.01 57.53,10.01 v56.9,10.64 | v86.11,29.69 v86.11,31.6 v86.11,29.69 | v86.11,11.91 v86.11,13.82
  Bottom 0.813: v34.67,46.2 IC2.22 C45.1 27.05,48.74 25.78,50.01 JP4.3 13.72,50.01 | v38.48,48.74 IC2.8 | 21.34,66.52 25.15,66.52 26.42,67.79 26.42,70.33 25.15,71.6 v21.34,71.6 J2.5 | 21.34,66.52 R33.A 21.34,61.44 C47.2 | J1.C32 J1.A32 157.23,10.64 157.23,13.18 | 157.23,58.9 J1.A13 | 157.23,61.44 J1.A12 | 157.23,56.36 J1.A14 | 157.23,53.82 J1.A15 | 157.23,51.28 J1.A16 | 157.23,48.74 J1.A17 | 157.23,46.2 J1.A18 | 157.23,43.66 J1.A19 | 157.23,30.96 J1.A24 | 157.23,28.42 J1.A25 | 157.23,25.88 J1.A26 | 157.23,23.34 J1.A27 | 157.23,20.8 J1.A28 | 157.23,18.26 J1.A29 | J1.A30 157.23,15.72 157.23,14.45 157.23,13.18 | 54.36,27.15 SV1.31 54.36,29.69 | 54.36,29.69 SV1.29 54.36,32.23 | 54.36,32.23 SV1.27 | SV1.25 54.36,37.31 | 54.36,37.31 SV1.23 54.36,39.85 | 54.36,39.85 SV1.21 54.36,42.39 | 54.36,42.39 SV1.19 | SV1.17 54.36,47.47 | SV1.2 SV1.1 54.36,65.25 SV1.3 54.36,62.71 SV1.5 54.36,60.17 SV1.7 54.36,57.63 SV1.9 54.36,55.09 SV1.11 54.36,52.55 SV1.13 54.36,50.01 SV1.15 54.36,47.47 | 157.23,13.18 J1.A31 | v56.9,10.64 56.9,23.34 SV1.33 54.36,27.15 | 54.36,27.15 54.36,29.69 | 54.36,29.69 54.36,32.23 | 54.36,32.23 54.36,34.77 54.36,37.31 | 54.36,37.31 54.36,39.85 | 54.36,39.85 54.36,42.39 | 54.36,42.39 54.36,44.93 54.36,47.47 | v86.11,65.89 v86.11,67.79 | v86.11,11.91 v86.11,13.82 | v86.11,29.69 v86.11,31.6 | v86.11,48.11 v86.11,50.01 | LED1.K LED2.K | IC1.15 19.43,30.96 19.43,41.12 16.26,41.12 | 13.72,50.01 C50.1 | 13.72,50.01 C49.1 | 2.29,50.01 13.72,50.01 | 9.91,41.12 16.26,41.12 | 9.91,41.12 9.91,44.93 | X1.5 9.91,32.23 2.29,32.23 | 2.29,41.12 9.91,41.12 | 2.29,27.79 2.29,28.01 | C36.2 12.45,16.99 2.29,16.99 | 2.29,21.44 2.29,21.21 | 32.77,5.56 IC6.7 | IC5.GND 32.77,84.3
  Bottom 0.813: 32.77,84.3 C1.2 | 32.77,84.3 C2.2 | 16.26,41.12 C41.1 | 56.9,84.3 62.61,84.3 | 50.55,94.46 v50.55,91.92 | 62.61,84.3 65.15,84.3 | 65.15,84.3 65.15,86.84 C5.2 | 65.15,84.3 R3.2 | 62.61,84.3 R2.2 | 62.61,84.3 C4.2 | 16.26,41.12 JP4.5 | C66.- 34.04,71.6 v21.34,84.3 17.53,88.11 17.53,94.46 | 21.34,66.52 J2.1 | J2.16 14.35,84.3 13.72,83.67 2.29,83.67
  Bottom 1.016: 86.11,94.46 v86.11,91.92
  Bottom 1.27: LED2.K LED1.K 2.29,89.38 | 2.29,32.23 2.29,27.79 2.29,21.44 2.29,16.99 | 2.29,70.33 S1.2 | 44.2,84.3 IC5.GND | v57.14,84.33 56.92,84.33 56.9,84.3 56.88,84.32 v44.03,84.32
  Bottom 1.422: 2.29,56.36 2.29,61.44 2.29,70.33 2.29,83.67 2.29,89.38 2.29,94.46 17.53,94.46 50.55,94.46 86.11,94.46 v157.23,94.46 157.23,57.63 157.23,55.09 157.23,52.55 157.23,47.47 157.23,44.93 157.23,42.39 157.23,39.85 157.23,29.69 157.23,27.15 157.23,24.61 157.23,22.07 157.23,19.53 157.23,16.99 157.23,10.64 v157.23,5.56 v86.11,5.56 32.77,5.56 2.29,5.56 2.29,16.99 2.29,32.23 2.29,41.12 2.29,43.66 | 2.29,56.36 v6.1,56.36 | 2.29,56.36 2.29,50.01 2.29,43.66 | 2.29,43.66 v6.1,43.66
N$2  (via drill 0.6 pad 1.42)
  Bottom 0.813: C1.1 32.77,87.48 28.96,87.48 | 28.96,87.48 28.32,87.48 | 28.96,87.48 IC5.IN | 62.61,89.38 C4.1
  Bottom 1.27: 28.96,91.92 28.96,87.48 | R35.2 28.96,91.92 | 72.14,89.38 D1.C | 72.14,89.38 IC3.3 | 28.96,91.92 28.96,89.38 62.61,89.38 72.14,89.38
  other vias: 21.34,91.92
N$3  (via drill 0.9 pad 1.93)
  other vias: 136.91,89.38
N$4  (via drill 0.9 pad 1.93)
  other vias: 129.29,89.38
N$5
  Bottom 0.813: R46.2 J2.15
N$7
  Bottom 0.254: IC2.11 39.75,56.36 37.85,54.46 37.85,53.19 37.21,52.55 31.5,52.55 27.69,56.36 19.43,56.36 13.08,62.71 13.08,71.6 9.27,75.41 S1.1
N$9
  Bottom 0.406: 70.87,34.77 70.87,30.33 IC4.6 C25.+ | 70.87,34.77 C27.2 | 70.87,34.77 70.23,34.77 70.23,36.68 R41.2
N$10  (via drill 0.6 pad 1.42, 0.9 pad 1.68)  (1 unrouted)
  Bottom 0.254: IC2.4 39.75,38.58 35.31,43.03 35.31,44.3 34.67,44.93 21.34,44.93 20.7,45.57 v20.7,46.84 | 9.91,52.55 8.32,50.97 6.41,50.97 v4.83,52.55 | JP4.2 20.07,52.55 v20.7,53.19
  Bottom 0.406: 13.72,52.55 JP4.2 | 9.91,52.55 13.72,52.55 | 13.72,52.55 C49.2
N$11  (via drill 0.6 pad 1.42, 0.9 pad 1.68)  (1 unrouted)
  Bottom 0.254: v24.51,53.19 27.69,53.19 30.86,50.01 35.31,50.01 37.85,47.47 37.85,45.57 39.75,43.66 IC2.6 | 13.72,47.47 C50.2 | 9.91,47.47 8.32,49.06 6.41,49.06 v4.83,47.47 | 17.53,47.47 18.16,47.47 19.43,48.74 23.88,48.74 24.51,48.11 v24.51,46.84
  Bottom 0.406: 17.53,47.47 JP4.4 13.72,47.47 9.91,47.47
N$12
  Bottom 1.27: D1.A J1.C1 J1.A1
N$13
  Bottom 0.406: C8.+ IC7.6 70.87,13.18 70.87,17.63 | 70.87,17.63 C7.2 | 70.87,17.63 70.23,17.63 70.23,19.53 R11.2
N$14
  Bottom 0.406: IC8.3 116.59,51.92 116.59,53.19 | 116.59,55.73 R4.1 R7.2 116.59,53.19 | 116.59,53.19 C28.+
N$15
  Bottom 0.813: 67.69,81.76 IC3.1 | 67.69,81.76 R1.2 | 65.15,81.76 67.69,81.76 | 65.15,81.76 R3.1 | R2.1 62.61,81.76 65.15,81.76
N$16  (via drill 1 pad 1.78)
  other vias: 16.26,71.6
N$17
  Bottom 0.406: 113.41,58.27 R8.1 114.68,58.27 114.68,57 | R57.2 121.67,57 114.68,57 | 114.68,56.36 C6.1 | 114.68,56.36 114.68,57 | IC8.2 114.68,53.19 114.68,56.36
N$18
  Bottom 0.406: IC8.6 109.6,51.92 109.6,56.36 | 109.6,56.36 C9.+ | R8.2 109.6,58.27 109.6,56.36 | 109.6,56.36 C6.2
N$19
  Bottom 0.406: R9.1 R17.2 116.59,70.97 | 116.59,70.97 116.59,69.7 IC9.3 112.14,69.7 | 116.59,70.97 C24.+
N$20
  Bottom 0.406: C17.+ IC13.6 70.87,46.2 70.87,50.65 | 70.87,50.65 C16.2 | 70.87,50.65 70.23,50.65 70.23,52.55 R29.2
N$21  (via drill 1 pad 1.78)
  other vias: 16.26,69.06
N$22
  Bottom 0.406: IC13.2 72.14,47.47 72.14,50.65 | 72.14,50.65 C16.1 | 72.14,50.65 72.77,50.65 72.77,52.55 | R56.2 83.57,51.28 74.68,51.28 74.68,52.55 72.77,52.55 | 72.77,52.55 R29.1
N$23  (via drill 1 pad 1.78)
  other vias: 16.26,66.52
N$24
  Bottom 0.406: R51.2 77.22,63.98 | IC14.3 77.22,62.08 77.22,63.35 | 77.22,65.89 R48.1 R51.2 | 77.22,63.35 R51.2 | 77.22,63.35 C21.+
N$25
  Bottom 0.406: C20.+ IC14.6 70.87,62.08 70.87,66.52 | 70.87,66.52 C19.2 | 70.87,66.52 70.23,66.52 70.23,68.43 R47.2
N$27
  Bottom 0.406: IC7.3 77.22,13.18 77.22,14.45 | 77.22,16.99 R12.1 R16.2 77.22,14.45 | 77.22,14.45 C23.+
N$29
  Bottom 0.406: IC9.6 109.6,69.7 109.6,74.14 | R18.2 109.6,76.05 109.6,74.14 | 109.6,74.14 C10.+ | 109.6,74.14 C11.2
N$30
  Bottom 0.406: R101.2 103.25,37.31 96.27,37.31 | 96.27,37.31 96.27,38.58 R60.1 95,38.58 | 96.27,36.68 C30.1 | 96.27,36.68 96.27,37.31 | IC10.2 96.27,33.5 96.27,36.68
N$31
  Bottom 0.406: IC10.3 98.17,32.23 98.17,33.5 | R64.1 R63.2 98.17,33.5 | 98.17,33.5 C51.+
N$32
  Bottom 0.406: 91.19,36.68 C54.+ | R60.2 91.19,38.58 91.19,36.68 | 91.19,36.68 91.19,32.23 IC10.6 | 91.19,36.68 C30.2
N$33
  Bottom 0.406: IC15.3 98.17,14.45 98.17,15.72 | 98.17,18.26 R66.1 R69.2 98.17,15.72 | 98.17,15.72 C46.+
N$35
  Bottom 0.406: IC11.3 116.59,33.5 116.59,34.77 | 116.59,37.31 R20.1 R23.2 116.59,34.77 | 116.59,34.77 C18.+
N$36
  Bottom 0.406: IC11.6 109.6,33.5 109.6,37.95 | R19.2 109.6,39.85 109.6,37.95 | 109.6,37.95 C13.+ | 111.51,37.95 C12.2 109.6,37.95
N$37
  Bottom 0.406: 114.68,37.95 114.68,34.77 IC11.2 | 114.68,37.95 114.68,38.58 | 114.68,38.58 114.68,39.85 R19.1 113.41,39.85 | 114.68,37.95 C12.1 | R52.2 121.67,38.58 114.68,38.58
N$38
  Bottom 0.406: IC15.6 91.19,14.45 91.19,18.9 | 93.09,18.9 C31.2 91.19,18.9 | 91.19,18.9 C57.+ | 91.19,18.9 91.19,20.8 R65.2 92.46,20.8
N$39
  Bottom 0.406: R103.2 103.25,19.53 96.27,19.53 | 96.27,19.53 96.27,20.8 R65.1 95,20.8 | 96.27,18.9 C31.1 | 96.27,18.9 96.27,19.53 | IC15.2 96.27,15.72 96.27,18.9
N$40
  Bottom 0.406: IC16.3 135.64,53.19 135.64,54.46 | R70.1 R73.2 135.64,54.46 | 135.64,54.46 C52.+
N$41
  Bottom 0.406: IC12.3 116.59,15.72 116.59,16.99 | 116.59,19.53 R25.1 R28.2 116.59,16.99 | 116.59,16.99 C29.+
N$42
  Bottom 0.406: 110.87,22.07 R24.2 109.6,22.07 109.6,20.17 | IC12.6 109.6,15.72 109.6,20.17 | 109.6,20.17 C14.2 | 109.6,20.17 C15.+
N$44
  Bottom 0.406: R105.2 140.72,57 139.45,58.27 133.73,58.27 | R74.1 133.73,59.54 133.73,58.27 | 133.73,57.63 C32.1 | 133.73,57.63 133.73,58.27 | IC16.2 133.73,54.46 133.73,57.63
N$45
  Bottom 0.406: IC16.6 128.65,53.19 128.65,57.63 | R74.2 128.65,59.54 128.65,57.63 | 130.56,57.63 C32.2 128.65,57.63 | 128.65,57.63 C59.+
N$46
  Bottom 0.406: R78.2 135.64,72.87 | IC17.3 135.64,70.97 135.64,72.24 | 135.64,74.78 R75.1 R78.2 | 135.64,72.24 R78.2 | 135.64,72.24 C48.+
N$47
  Bottom 0.406: IC13.3 77.22,46.2 77.22,47.47 | 77.22,50.01 R30.1 R40.2 77.22,47.47 | 77.22,47.47 C22.+
N$49
  Bottom 0.406: IC17.6 128.65,70.97 128.65,75.41 | R79.2 128.65,77.32 128.65,75.41 | 130.56,75.41 C33.2 128.65,75.41 | 128.65,75.41 C61.+
N$50
  Bottom 0.406: R107.2 140.72,74.78 139.45,76.05 133.73,76.05 | 132.46,77.32 R79.1 133.73,77.32 133.73,76.05 | 133.73,75.41 C33.1 | 133.73,75.41 133.73,76.05 | IC17.2 133.73,72.24 133.73,75.41
N$52
  Bottom 0.406: R84.2 135.64,36.68 | IC18.3 135.64,34.77 135.64,36.04 | R84.2 R81.1 | 135.64,36.04 R84.2 | 135.64,36.04 C40.+
N$53
  Bottom 0.406: IC18.6 128.65,34.77 128.65,39.22 | R80.2 128.65,41.12 128.65,39.22 | 128.65,39.22 C34.2 | 128.65,39.22 C55.+
N$54
  Bottom 0.406: R100.2 140.72,38.58 139.45,39.85 133.73,39.85 | 133.73,39.85 133.73,41.12 R80.1 132.46,41.12 | 133.73,39.22 C34.1 | 133.73,39.22 133.73,39.85 | IC18.2 133.73,36.04 133.73,39.22
N$55
  Bottom 0.406: R89.2 135.64,18.9 | IC19.3 135.64,16.99 R89.2 | 135.64,20.8 R86.1 R89.2 | R89.2 138.18,18.49 C53.+
N$56
  Bottom 0.254: IC2.15 32.77,65.89 25.15,73.51 18.16,73.51 J2.6
N$57
  Bottom 0.254: IC2.16 33.4,61.44 35.31,63.35 35.31,64.62 20.7,79.22 J2.11
N$59
  Bottom 0.254: IC2.17 33.4,58.9 35.94,61.44 35.94,65.25 20.7,80.49 17.53,80.49 J2.12
N$61
  Bottom 0.254: IC2.18 33.4,56.36 36.58,59.54 36.58,65.89 20.7,81.76 J2.13
N$62  (via drill 0.6 pad 1.42)
  Top 0.406: v35.94,53.82 v35.94,56.36
  Bottom 0.254: v35.94,56.36 37.21,57.63 37.21,66.52 20.7,83.03 17.53,83.03 J2.14 | IC2.19 v35.94,53.82
N$64  (via drill 2.8 pad 3.81)
  other vias: 8.64,11.91
N$65
  Bottom 0.406: IC19.6 128.65,16.99 128.65,21.44 | 130.56,21.44 C35.2 128.65,21.44 | 128.65,21.44 C56.+ | R85.2 128.65,23.34 128.65,21.44
N$66
  Bottom 0.406: R102.2 140.72,20.8 139.45,22.07 133.73,22.07 | 133.73,22.07 133.73,23.34 R85.1 | 133.73,21.44 C35.1 | 133.73,21.44 133.73,22.07 | IC19.2 133.73,18.26 133.73,21.44
N$70
  Bottom 0.406: LED1.A 4.83,85.57 5.46,84.94 13.08,84.94 13.72,85.57 R34.2
N$71  (via drill 2.8 pad 3.81)
  other vias: 8.63,37.09
N$73  (via drill 2.8 pad 6.45)
  other vias: 3.52,5.51
N$74
  Bottom 0.406: IC20.3 98.17,50.65 98.17,51.92 | R94.2 98.17,52.55 | 98.17,54.46 R91.1 R94.2 | 98.17,51.92 R94.2 | 98.17,51.92 C42.+
N$75
  Bottom 0.406: IC20.6 91.19,50.65 91.19,55.09 | R90.2 91.19,57 91.19,55.09 | 91.19,55.09 C37.2 | 91.19,55.09 C58.+
N$77
  Bottom 0.406: 95,57 R90.1 96.27,57 96.27,55.73 | R104.2 103.25,55.73 96.27,55.73 | 96.27,55.09 C37.1 | 96.27,55.09 96.27,55.73 | IC20.2 96.27,51.92 96.27,55.09
N$78
  Bottom 0.406: IC21.3 98.17,68.43 98.17,69.7 | 98.17,72.24 R96.1 R99.2 98.17,69.7 | 98.17,69.7 C39.+
N$79
  Bottom 0.406: IC21.6 91.19,68.43 91.19,72.87 | 91.19,72.87 91.19,74.78 R95.2 | 91.19,72.87 C38.2 | 91.19,72.87 C60.+
N$80  (via drill 2.8 pad 6.45)
  other vias: 3.54,94.55
N$83
  Bottom 0.406: 93.73,69.7 IC21.2 96.27,69.7 96.27,72.87 | 95,74.78 R95.1 96.27,74.78 96.27,73.51 | R106.2 103.25,73.51 96.27,73.51 | 96.27,72.87 C38.1 | 96.27,72.87 96.27,73.51
N$84
  Bottom 0.406: IC9.2 114.68,70.97 114.68,74.14 | 112.78,74.14 C11.1 114.68,74.14 | 114.68,74.14 114.68,74.78 | 113.41,76.05 R18.1 114.68,76.05 114.68,74.78 | R59.2 121.67,74.78 114.68,74.78
N$85
  Bottom 0.406: IC4.2 72.14,31.6 72.14,34.77 | 72.14,34.77 C27.1 | 72.14,34.77 72.77,34.77 72.77,36.68 | R53.2 83.57,30.96 79.12,35.41 74.68,35.41 74.68,36.68 72.77,36.68 | 72.77,36.68 R41.1
N$89
  Bottom 0.813: J2.3 R33.S
N$91
  Bottom 0.406: LED2.A R35.1
N$93  (via drill 0.6 pad 1.42)
  other vias: 13.72,89.38
N$97
  Bottom 0.406: IC7.2 72.14,14.45 72.14,17.63 | 72.14,17.63 C7.1 | 72.14,17.63 72.77,17.63 72.77,19.53 R11.1 74.68,19.53 74.68,18.26 79.12,18.26 83.57,13.82 R55.2
N$108
  Bottom 0.406: R54.2 121.67,20.8 114.68,20.8 | 114.68,20.8 114.68,22.07 R24.1 113.41,22.07 | 114.68,20.17 C14.1 | 114.68,20.17 114.68,20.8 | IC12.2 114.68,16.99 114.68,20.17
N$110
  Bottom 0.406: IC14.2 72.14,63.35 72.14,66.52 | 72.14,66.52 C19.1 | 72.14,66.52 72.77,66.52 72.77,68.43 R47.1 74.68,68.43 74.68,67.16 83.57,67.16 R58.2
N$126
  Bottom 0.406: IC1.12 23.88,23.34 25.78,25.25 34.67,25.25 39.12,20.8 IC6.13
N$127
  Bottom 0.406: C44.2 IC1.1
N$129
  Bottom 0.406: C44.1 IC1.3
N$130
  Bottom 0.406: C43.2 IC1.4
N$131
  Bottom 0.406: C43.1 IC1.5
N$132
  Bottom 0.406: C3.2 17.53,34.77 17.53,32.23 16.26,30.96 IC1.2
N$133
  Bottom 0.406: C36.1 IC1.6
N$134
  Bottom 0.406: IC1.9 28.32,15.72 29.59,16.99 29.59,22.07 30.86,23.34 IC6.1
N$135
  Bottom 0.254: IC1.11 20.7,20.8 19.18,19.28 19.18,13.44 20.7,11.91 35.31,11.91 36.58,13.18 IC6.10 41.02,13.18
  Bottom 0.406: IC1.11 R36.1
N$136
  Bottom 0.254: X1.8 7.37,26.01 10.54,26.01 11.81,24.61 18.8,24.61 IC1.14
N$137
  Bottom 0.254: X1.7 7.49,23.22 10.67,23.22 11.81,22.07 18.8,22.07 IC1.13
N$138  (via drill 0.6 pad 1.27)
  Top 0.406: v17.53,16.99 v17.53,27.15
  Bottom 0.254: 9.91,27.15 10.03,27.28 9.78,27.28 9.91,27.15 | 9.91,27.15 X1.4 | v17.53,27.15 9.91,27.15 | 17.53,16.36 v17.53,16.99
  Bottom 0.406: 17.53,16.36 16.89,15.72 IC1.8
N$139
  Bottom 0.254: 9.91,19.53 13.08,19.53 14.35,18.26 IC1.7
  Bottom 0.406: X1.1 9.91,19.53 7.37,19.53 X1.6
N$142
  Bottom 0.254: IC2.14 39.12,63.98 38.48,63.35 38.48,57 36.58,55.09 30.86,55.09 28.32,57.63 19.43,57.63 14.35,62.71 14.35,68.43 14.99,69.06 J2.4
N$145
  Bottom 0.254: 41.02,10.64 42.93,10.64 42.93,14.45 36.58,14.45 35.31,15.72 IC6.4 30.86,15.72 28.96,13.82 21.34,13.82 20.07,15.09 20.07,17.63 20.7,18.26 IC1.10
  Bottom 0.406: IC1.10 26.42,18.26 27.69,19.53 R37.1
N$152
  Bottom 0.406: IC4.3 77.22,30.33 77.22,31.6 | 77.22,34.14 R45.1 R44.2 77.22,31.6 | 77.22,31.6 C26.+
N$162  (via drill 0.9 pad 1.68)
  other vias: 4.83,50.01
N$169  (via drill 0.6 pad 1.42)
  other vias: 12.45,33.5
N$173  (via drill 0.6 pad 1.42)
  other vias: 13.72,91.92
N$177  (via drill 0.6 pad 1.42)
  other vias: 13.72,86.84
N$193  (via drill 0.6 pad 1.42)
  other vias: 12.45,28.42
N$195  (via drill 0.6 pad 1.42)
  other vias: 25.15,20.8
N$200  (via drill 0.6 pad 1.42)
  other vias: 27.69,20.8
N$214  (via drill 0.6 pad 1.42)
  other vias: 16.26,38.58
N$218  (via drill 0.6 pad 1.42)
  other vias: 25.15,30.96
N$219  (via drill 0.6 pad 1.42)
  other vias: 27.69,30.96
N$220  (via drill 0.6 pad 1.42)
  other vias: 25.15,38.58
N$221  (via drill 0.6 pad 1.42)
  other vias: 27.69,38.58
N$222  (via drill 0.6 pad 1.42)
  other vias: 27.69,28.42
N$223  (via drill 0.6 pad 1.42)
  other vias: 25.15,28.42
N$226  (via drill 0.6 pad 1.42)
  other vias: 35.31,18.26
N$228  (via drill 0.6 pad 1.42)
  other vias: 17.53,16.99
N$229  (via drill 0.6 pad 1.42)
  other vias: 17.53,27.15
N$236  (via drill 0.9 pad 1.68)
  Bottom 0.254: IC2.5 39.75,41.12 36.58,44.3 36.58,46.2 35.31,47.47 30.86,47.47 27.05,51.28 23.88,51.28 22.61,52.55 22.61,54.46 21.97,55.09 JP4.1 9.91,55.09 v7.37,52.55
N$237  (via drill 0.6 pad 1.42)
  other vias: 21.34,38.58
N$241  (via drill 0.6 pad 1.42)
  other vias: 7.37,20.49
N$242  (via drill 0.6 pad 1.42)
  other vias: 9.9,21.87
N$243  (via drill 0.6 pad 1.42)
  other vias: 9.92,24.6
N$244  (via drill 0.6 pad 1.42)
  other vias: 7.35,23.24
N$245  (via drill 0.6 pad 1.42)
  other vias: 21.34,86.84
N$246  (via drill 0.6 pad 1.42)
  other vias: 21.34,89.38
N$247  (via drill 0.6 pad 1.42)
  other vias: 7.37,25.99
N$250  (via drill 0.6 pad 1.42)
  other vias: 16.26,36.04
N$251  (via drill 0.6 pad 1.42)
  other vias: 21.34,36.04
N$254  (via drill 0.6 pad 1.42)
  other vias: 9.9,27.36
N$255  (via drill 0.6 pad 1.42)
  other vias: 9.92,19.12
N$256  (via drill 0.6 pad 1.27)
  other vias: 12.45,20.81
N$257  (via drill 0.6 pad 1.27)
  other vias: 12.45,18.25
N$258  (via drill 0.6 pad 1.42)
  other vias: 7.37,28.71
N$259  (via drill 0.6 pad 1.42)
  other vias: 9.92,30.09
N$260  (via drill 1 pad 1.78)
  other vias: 16.26,84.3
N$265  (via drill 1 pad 1.78)
  other vias: 16.26,81.76
N$266  (via drill 1 pad 1.78)
  other vias: 16.26,79.22
N$267  (via drill 0.6 pad 1.68)
  other vias: 13.72,86.84
N$268  (via drill 0.6 pad 1.68)
  other vias: 21.34,89.38
N$269  (via drill 0.6 pad 1.68)
  other vias: 13.72,91.92
N$270  (via drill 0.6 pad 1.68)
  other vias: 21.34,91.92
N$271  (via drill 0.6 pad 1.68)
  other vias: 13.72,89.38
N$272  (via drill 0.6 pad 1.68)
  other vias: 21.34,86.84
N$281  (via drill 0.6 pad 1.68)
  other vias: 18.8,66.52
NF1
  Bottom 0.254: J1.C25 145.8,28.42 144.53,29.69 121.67,29.69 R52.1 121.67,30.96
NF2
  Bottom 0.254: J1.C27 145.8,23.34 141.99,27.15 84.2,27.15 83.57,27.79 R53.1
NF3
  Bottom 0.254: J1.C29 147.07,18.26 140.72,11.91 121.67,11.91 R54.1
NF4
  Bottom 0.254: J1.C31 147.07,13.18 143.26,9.37 84.2,9.37 83.57,10.01 R55.1
NF5
  Bottom 0.254: J1.C19 145.8,43.66 144.53,44.93 84.2,44.93 83.57,45.57 R56.1
NF6
  Bottom 0.254: R57.1 121.67,48.74 J1.C17
NF7
  Bottom 0.254: J1.C15 148.34,53.82 138.81,63.35 84.2,63.35 83.57,63.98 R58.1
NF8
  Bottom 0.254: J1.C13 148.34,58.9 141.35,65.89 121.67,65.89 R59.1
NF9
  Bottom 0.254: R100.1 140.72,31.6 141.35,30.96 J1.C24
NF10
  Bottom 0.254: J1.C26 145.8,25.88 143.26,28.42 103.25,28.42 R101.1
NF11
  Bottom 0.254: J1.C28 147.07,20.8 141.99,15.72 R102.1
NF12
  Bottom 0.254: J1.C30 147.07,15.72 141.99,10.64 103.25,10.64 R103.1
NF13
  Bottom 0.254: J1.C18 145.8,46.2 145.16,46.84 103.25,46.84 R104.1
  Bottom 0.406: R104.1 103.48,47.88
NF14
  Bottom 0.254: J1.C16 141.35,51.28 140.72,51.92 R105.1
NF15
  Bottom 0.254: J1.C14 148.34,56.36 140.08,64.62 103.25,64.62 R106.1
NF16
  Bottom 0.254: J1.C12 148.34,61.44 140.72,69.06 R107.1
RESET  (via drill 0.6 pad 1.42)
  Top 0.406: v45.47,29.06 v45.47,36.04
  Bottom 0.254: J1.C6 141.99,84.3 80.39,84.3 74.68,78.59 47.37,78.59 46.1,77.32 46.1,36.68 v45.47,36.04
  Bottom 0.406: v45.47,29.06 43.56,30.96 IC2.1
S$1  (via drill 1 pad 1.78)
  other vias: 16.26,71.6
S$3  (via drill 1 pad 1.78)
  other vias: 18.8,69.06
S$4  (via drill 1 pad 1.78)
  other vias: 18.8,71.6
SCL  (via drill 0.6 pad 1.42)
  Top 0.406: v42.93,25.25 v42.93,39.85
  Bottom 0.254: J1.C4 147.7,81.76 143.89,85.57 79.12,85.57 73.41,79.86 46.1,79.86 44.83,78.59 44.83,41.76 v42.93,39.85 | v42.93,25.25 42.93,18.9 42.29,18.26 IC6.12
  Bottom 0.406: v42.93,25.25 40.39,27.79 34.67,27.79 32.77,29.69 IC2.28 31.5,30.96 25.15,37.31 R38.1 | IC6.11 IC6.12
SDA  (via drill 0.6 pad 1.27, 0.6 pad 1.42)
  Top 0.406: v35.31,18.26 v35.31,30.96 | v44.2,27.15 v44.2,37.95
  Bottom 0.254: v44.2,37.95 45.47,39.22 45.47,77.95 46.74,79.22 74.04,79.22 79.76,84.94 143.26,84.94 148.97,79.22 J1.C5
  Bottom 0.406: IC6.2 IC6.3 v35.31,18.26 | v44.2,27.15 42.29,29.06 37.21,29.06 v35.31,30.96 35.31,32.87 34.67,33.5 IC2.27 31.5,33.5 27.69,37.31 R39.1
VCC  (via drill 0.6 pad 1.42)
  Top 0.406: v29.59,66.52 v40.39,66.52 | v29.59,41.12 v29.59,58.9
  Bottom 0.813: C47.1 26.42,61.44 R33.E 29.59,63.98 | C2.1 32.77,81.13 28.96,81.13 | 28.96,81.13 28.32,81.13 | 29.59,63.98 v29.59,58.9 20.07,58.9 16.26,62.71 J2.2 | 28.96,81.13 28.96,79.22 30.23,77.95 36.58,77.95 | 28.96,81.13 IC5.OUT 26.42,81.76 25.15,83.03 25.15,85.57 23.88,86.84 R34.1 R46.1 | 29.59,63.98 v29.59,66.52 | 36.58,77.95 41.66,77.95 42.93,76.68 42.93,66.52 | 42.93,66.52 42.93,46.2 IC2.7 | R37.2 27.69,26.52 37.21,26.52 IC6.14 | R38.2 R39.2 R37.2 | R37.2 R36.2 25.15,33.5 IC1.16 21.34,33.5 C3.1 C41.2 21.34,41.12 27.05,41.12 | v40.39,66.52 42.93,66.52 | 27.05,41.12 v29.59,41.12 | 27.05,41.12 C45.2 | 36.58,77.95 C66.+
(copper drawn outside any net)
  shapes: Bottom area x8

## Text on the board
Bottom: A-MUX-STa
Document: +12V | +8V | 16 | 16 | 8 | 15 | 15 | 7 | 7 | 14 | 14 | 6 | 6 | 13 | 13 | 5 | 5 | 9 | 1 | 10 | DA | EN | 2 | CL | 11 | 9 | 3 | 1 | 12 | 10 | 4 | 2 | 11 | 3 | 12 | 4
tDocu: SCL | SDA | LCD | 8 | 8 | Audio Multiplexer Steuerung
